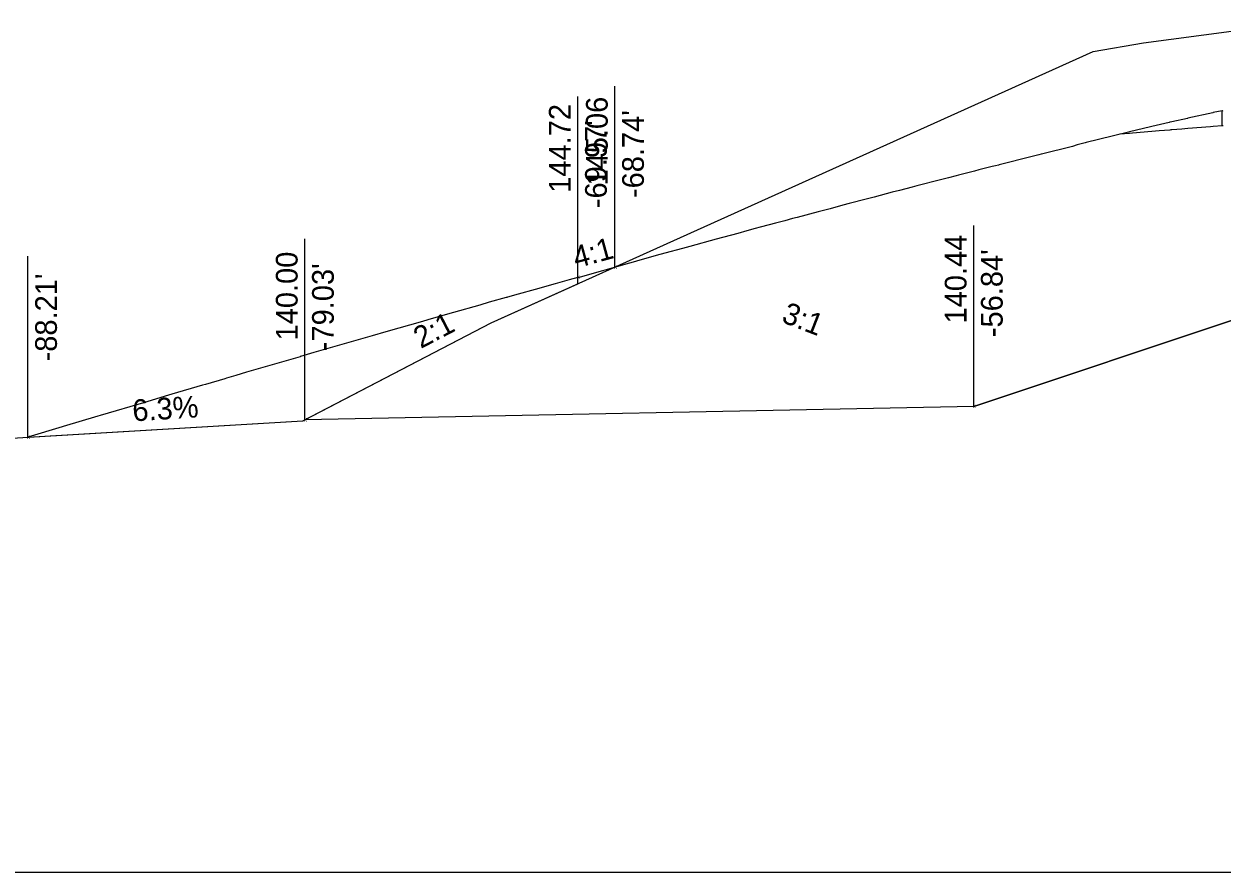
# Model space of a CAD drawing. Extents: x -100 to 7529, y -13 to 10775.
# Drawn here: x 3061.66 to 3101.4, y 5500 to 5528.12 of the extents above; entities that cross this region are included whole.
import ezdxf

# ---------------------------------------------------------------- set-up
doc = ezdxf.new("R2010")
doc.units = 0
for name, color, linetype in [('DTM_CONTOURS_MINOR', 7, 'Continuous'), ('DTM_X_GROUND', 7, 'Continuous'), ('X_PROFILES_1', 7, 'Continuous'), ('XS_CELL', 7, 'Continuous'), ('XS_M_SHAPES_EARTHWORK', 7, 'Continuous'), ('XS_P_DR_GRAVEL', 7, 'Continuous'), ('XS_P_GROUND', 7, 'Continuous'), ('XS_P_TX_CLEARZONE', 7, 'Continuous'), ('XS_P_TX_FS_BS', 7, 'Continuous')]:
    doc.layers.add(name, color=color, linetype=linetype)

msp = doc.modelspace()

# ---------------------------------------------------------------- linework, layer by layer
at = {"layer": 'DTM_X_GROUND'}
msp.add_lwpolyline([(3000, 5512.2), (3044.132, 5513.453), (3046.486, 5513.62), (3053.808, 5513.95), (3070.909, 5514.966), (3077.153, 5518.209), (3097.118, 5527.209), (3098.789, 5527.5), (3101.713, 5527.882), (3110.312, 5528.066), (3113.777, 5528.123), (3116.864, 5528.039), (3124.572, 5527.826)], dxfattribs=at)
at = {"layer": 'XS_CELL'}
msp.add_line((3000, 5500), (3150, 5500), dxfattribs=at)
msp.add_line((3000, 5500), (3150, 5500), dxfattribs=at)
at = {"layer": 'XS_M_SHAPES_EARTHWORK'}
for points in [[(3070.973, 5514.999), (3077.153, 5518.209), (3097.118, 5527.209), (3098.789, 5527.5), (3101.713, 5527.882), (3110.312, 5528.066), (3113.777, 5528.123), (3116.864, 5528.039), (3124.572, 5527.826), (3125.877, 5527.605), (3129.562, 5526.928), (3131.005, 5526.033), (3126.052, 5525.901), (3120, 5524.389), (3093.161, 5515.443)], [(3061.789, 5514.424), (3070.909, 5514.966), (3077.153, 5518.209), (3080.029, 5519.505), (3080.029, 5519.721), (3079.738, 5519.637), (3079.281, 5519.504), (3078.61, 5519.321), (3078.045, 5519.165), (3077.701, 5519.065), (3077.671, 5519.056), (3077.653, 5519.051), (3077.086, 5518.894), (3076.776, 5518.802), (3075.9, 5518.557), (3075.477, 5518.433), (3075.055, 5518.314), (3074.872, 5518.26), (3073.655, 5517.915), (3073.202, 5517.78), (3072.971, 5517.714), (3072.894, 5517.691), (3071.277, 5517.228), (3070.834, 5517.094), (3070.823, 5517.091), (3070.82, 5517.09), (3069.034, 5516.573), (3068.688, 5516.468), (3068.375, 5516.376), (3068.322, 5516.36), (3067.676, 5516.172), (3067.58, 5516.142), (3066.566, 5515.845), (3066.448, 5515.809), (3065.76, 5515.606), (3065.695, 5515.586), (3064.189, 5515.141), (3064.106, 5515.115), (3062.957, 5514.773), (3062.927, 5514.764)]]:
    msp.add_lwpolyline(points, close=True, dxfattribs=at)
at = {"layer": 'XS_P_DR_GRAVEL'}
for points in [[(3101.435, 5524.75), (3101.397, 5524.747), (3101.397, 5525.247), (3101.435, 5525.25)], [(3101.397, 5524.747), (3101.103, 5524.723), (3101.014, 5524.715), (3100.265, 5524.653), (3100.065, 5524.637), (3099.734, 5524.609), (3099.703, 5524.607), (3099.67, 5524.604), (3099.31, 5524.574), (3099.069, 5524.554), (3098.428, 5524.502), (3098.331, 5524.494), (3098.004, 5524.467)]]:
    msp.add_lwpolyline(points, dxfattribs=at)
at = {"layer": 'XS_P_GROUND'}
for points in [[(3093.161, 5515.443), (3120, 5524.389), (3120, 5524.389), (3120, 5524.389), (3132, 5527.389)], [(3101.397, 5525.247), (3101.103, 5525.183), (3101.097, 5525.181), (3100.265, 5524.998), (3100.25, 5524.993), (3099.734, 5524.877), (3099.731, 5524.876), (3099.67, 5524.863), (3099.644, 5524.854), (3099.069, 5524.723), (3099.025, 5524.708), (3098.331, 5524.547), (3098.292, 5524.534), (3097.846, 5524.429), (3097.757, 5524.399), (3096.89, 5524.19), (3096.855, 5524.179), (3096.596, 5524.115), (3096.441, 5524.064), (3095.41, 5523.806), (3095.395, 5523.801), (3095.315, 5523.781), (3095.096, 5523.729), (3094.003, 5523.451), (3093.98, 5523.446), (3093.888, 5523.422), (3093.775, 5523.396), (3093.334, 5523.282), (3093.186, 5523.246), (3092.657, 5523.109), (3092.577, 5523.09), (3092.32, 5523.023), (3092.059, 5522.959), (3091.275, 5522.753), (3091.117, 5522.714), (3090.703, 5522.605), (3090.453, 5522.543), (3089.855, 5522.383), (3089.594, 5522.318), (3089.033, 5522.167), (3088.816, 5522.113), (3088.394, 5521.998), (3088.001, 5521.898), (3087.306, 5521.709), (3087.146, 5521.668), (3086.89, 5521.598), (3086.582, 5521.518), (3086.121, 5521.391), (3085.868, 5521.325), (3085.519, 5521.228), (3085.441, 5521.208), (3085.34, 5521.18), (3084.616, 5520.99), (3083.741, 5520.745), (3083.704, 5520.735), (3083.665, 5520.724), (3082.751, 5520.478), (3082.088, 5520.291), (3081.862, 5520.229), (3081.74, 5520.194), (3080.034, 5519.706)], [(3101.397, 5525.247), (3101.103, 5525.183), (3101.097, 5525.181), (3100.265, 5524.998), (3100.25, 5524.993), (3099.734, 5524.877), (3099.731, 5524.876), (3099.67, 5524.863), (3099.644, 5524.854), (3099.069, 5524.723), (3099.025, 5524.708), (3098.331, 5524.547), (3098.292, 5524.534), (3097.846, 5524.429), (3097.757, 5524.399), (3096.89, 5524.19), (3096.855, 5524.179), (3096.596, 5524.115), (3096.441, 5524.064), (3095.41, 5523.806), (3095.395, 5523.801), (3095.315, 5523.781), (3095.096, 5523.729), (3094.003, 5523.451), (3093.98, 5523.446), (3093.888, 5523.422), (3093.775, 5523.396), (3093.334, 5523.282), (3093.186, 5523.246), (3092.657, 5523.109), (3092.577, 5523.09), (3092.32, 5523.023), (3092.059, 5522.959), (3091.275, 5522.753), (3091.117, 5522.714), (3090.703, 5522.605), (3090.453, 5522.543), (3089.855, 5522.383), (3089.594, 5522.318), (3089.033, 5522.167), (3088.816, 5522.113), (3088.394, 5521.998), (3088.001, 5521.898), (3087.306, 5521.709), (3087.146, 5521.668), (3086.89, 5521.598), (3086.582, 5521.518), (3086.121, 5521.391), (3085.868, 5521.325), (3085.519, 5521.228), (3085.441, 5521.208), (3085.34, 5521.18), (3084.616, 5520.99), (3083.741, 5520.745), (3083.704, 5520.735), (3083.665, 5520.724), (3082.751, 5520.478), (3082.088, 5520.291), (3081.862, 5520.229), (3081.74, 5520.194), (3081.259, 5520.057)], [(3080.029, 5519.721), (3079.738, 5519.637), (3079.281, 5519.504), (3078.61, 5519.321), (3078.045, 5519.165), (3077.701, 5519.065), (3077.671, 5519.056), (3077.653, 5519.051), (3077.086, 5518.894), (3076.776, 5518.802), (3075.9, 5518.557), (3075.477, 5518.433), (3075.055, 5518.314), (3074.872, 5518.26), (3073.655, 5517.915), (3073.202, 5517.78), (3072.971, 5517.714), (3072.894, 5517.691), (3071.277, 5517.228), (3070.834, 5517.094), (3070.823, 5517.091), (3070.82, 5517.09), (3069.034, 5516.573), (3068.688, 5516.468), (3068.375, 5516.376), (3068.322, 5516.36), (3067.676, 5516.172), (3067.58, 5516.142), (3066.566, 5515.845), (3066.448, 5515.809), (3065.76, 5515.606), (3065.695, 5515.586), (3064.189, 5515.141), (3064.106, 5515.115), (3062.957, 5514.773), (3062.927, 5514.764), (3061.789, 5514.424)], [(3080.029, 5519.721), (3079.738, 5519.637), (3079.281, 5519.504), (3078.61, 5519.321), (3078.045, 5519.165), (3077.701, 5519.065), (3077.671, 5519.056), (3077.653, 5519.051), (3077.086, 5518.894), (3076.776, 5518.802), (3075.9, 5518.557), (3075.477, 5518.433), (3075.055, 5518.314), (3074.872, 5518.26), (3073.655, 5517.915), (3073.202, 5517.78), (3072.971, 5517.714), (3072.894, 5517.691), (3071.277, 5517.228), (3070.834, 5517.094), (3070.823, 5517.091), (3070.82, 5517.09), (3069.034, 5516.573), (3068.688, 5516.468), (3068.375, 5516.376), (3068.322, 5516.36), (3067.676, 5516.172), (3067.58, 5516.142), (3066.566, 5515.845), (3066.448, 5515.809), (3065.76, 5515.606), (3065.695, 5515.586), (3064.189, 5515.141), (3064.106, 5515.115), (3062.957, 5514.773), (3062.927, 5514.764), (3061.789, 5514.424)], [(3093.161, 5515.443), (3070.973, 5514.999)]]:
    msp.add_lwpolyline(points, dxfattribs=at)
at = {"layer": 'XS_P_TX_CLEARZONE'}
for p, q in [((3081.259, 5520.057), (3081.259, 5526.057)), ((3081.259, 5520.057), (3081.259, 5526.057)), ((3080.029, 5519.721), (3080.029, 5525.721)), ((3080.029, 5519.721), (3080.029, 5525.721)), ((3093.161, 5515.443), (3093.161, 5521.443)), ((3093.161, 5515.443), (3093.161, 5521.443)), ((3070.973, 5514.999), (3070.973, 5520.999)), ((3070.973, 5514.999), (3070.973, 5520.999)), ((3061.789, 5514.424), (3061.789, 5520.424)), ((3061.789, 5514.424), (3061.789, 5520.424))]:
    msp.add_line(p, q, dxfattribs=at)

# ---------------------------------------------------------------- texts
at = {"layer": 'DTM_CONTOURS_MINOR'}
msp.add_text('X', height=0.12, dxfattribs=at).set_placement((3070.934, 5514.939))
at = {"layer": 'X_PROFILES_1'}
for p in [(3081.22, 5519.997), (3079.99, 5519.661), (3093.121, 5515.383), (3061.75, 5514.364)]:
    msp.add_text('X', height=0.12, dxfattribs=at).set_placement(p)
at = {"layer": 'XS_P_TX_CLEARZONE'}
for s, p in [('145.06', (3081.019, 5522.765)), ('145.06', (3081.019, 5522.765)), ('144.72', (3079.789, 5522.525)), ('144.72', (3079.789, 5522.525)), ("-68.74'", (3082.219, 5522.351)), ("-68.74'", (3082.219, 5522.351)), ("-69.97'", (3080.989, 5522.015)), ("-69.97'", (3080.989, 5522.015)), ('140.44', (3092.921, 5518.191)), ('140.44', (3092.921, 5518.191)), ('140.00', (3070.733, 5517.628)), ('140.00', (3070.733, 5517.628)), ("-56.84'", (3094.121, 5517.737)), ("-56.84'", (3094.121, 5517.737)), ("-79.03'", (3071.933, 5517.271)), ("-79.03'", (3071.933, 5517.271)), ("-88.21'", (3062.749, 5516.933)), ("-88.21'", (3062.749, 5516.933))]:
    msp.add_text(s, height=0.72, rotation=90, dxfattribs=at).set_placement(p)
at = {"layer": 'XS_P_TX_FS_BS'}
for s, rotation, p in [('4:1', 15.2624, (3079.975, 5520.017)), ('3:1', 338.8102, (3086.748, 5518.251)), ('2:1', 27.5371, (3074.82, 5517.343)), ('6.3%', 3.5853, (3065.274, 5514.943))]:
    msp.add_text(s, height=0.72, rotation=rotation, dxfattribs=at).set_placement(p)

doc.saveas('drawing.dxf')
